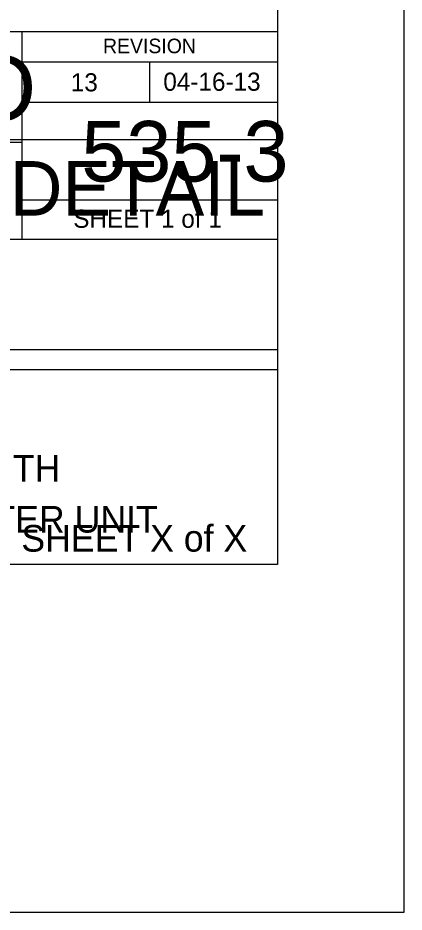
# Model space of a CAD drawing. Extents: x 10133 to 81668, y 2357 to 12713.
# Drawn here: x 13172 to 13490, y 3964 to 4703 of the extents above; entities that cross this region are included whole.
import ezdxf

# ---------------------------------------------------------------- set-up
doc = ezdxf.new("R2010")
doc.units = 0
for name, color, linetype in [('dsnNonPlotable', 7, 'Continuous'), ('dsnStdBlock', 7, 'Continuous'), ('dsnStdBorder', 7, 'Continuous'), ('dsnstdModifiedBlock', 7, 'Continuous'), ('Text', 7, 'Continuous')]:
    doc.layers.add(name, color=color, linetype=linetype)

msp = doc.modelspace()

# ---------------------------------------------------------------- linework, layer by layer
at = {"layer": 'dsnNonPlotable'}
msp.add_lwpolyline([(12697.77, 4691.26), (13385.79, 4691.26), (13385.79, 4251.25), (12697.77, 4251.25)], close=True, dxfattribs=at)
at = {"layer": 'dsnStdBlock'}
for p, q in [((13174.89, 4691.25), (13174.89, 4599.91)), ((13174.89, 4666.31), (13385.81, 4666.31)), ((13280.35, 4666.31), (13280.35, 4633.11)), ((13174.89, 4633.11), (13385.81, 4633.11)), ((12697.79, 4599.91), (13174.89, 4599.91)), ((13174.89, 4599.91), (13174.89, 4519.91)), ((13385.81, 4552.11), (13174.89, 4552.11)), ((12697.79, 4519.91), (13385.81, 4519.91)), ((12697.79, 4428.9), (13385.81, 4428.9))]:
    msp.add_line(p, q, dxfattribs=at)
msp.add_lwpolyline([(12697.79, 4691.25), (13385.81, 4691.25), (13385.81, 4251.24), (12697.79, 4251.24)], close=True, dxfattribs=at)
at = {"layer": 'dsnStdBorder'}
msp.add_lwpolyline([(10250.81, 6261.24), (13385.81, 6261.24), (13385.81, 4251.24), (10250.81, 4251.24)], close=True, dxfattribs=at)
at = {"layer": 'dsnstdModifiedBlock'}
for p, q in [((12697.79, 4602.16), (13385.81, 4602.16)), ((12697.79, 4412.15), (13385.81, 4412.15))]:
    msp.add_line(p, q, dxfattribs=at)
msp.add_lwpolyline([(12697.79, 4691.25), (13385.81, 4691.25), (13385.81, 4251.24), (12697.79, 4251.24)], close=True, dxfattribs=at)
at = {"layer": 'Text'}
msp.add_lwpolyline([(10146.31, 3964.24), (13490.31, 3964.24), (13490.31, 6548.24), (10146.31, 6548.24)], close=True, dxfattribs=at)

# ---------------------------------------------------------------- texts
at = {"layer": 'dsnStdBlock'}
for s, height, p in [('REVISION', 12, (13241.87, 4673.4)), ('13', 15, (13215.28, 4641.88)), ('04-16-13', 15, (13291.63, 4642.36)), ('535-3', 50, (13223.94, 4567.43)), ('ROAD DESIGN DETAIL', 45.0011, (12726.92, 4539.33)), ('SHEET 1 of 1', 15, (13217.3, 4529.26)), ('HOT MIX ASPHALT WITH', 22, (12858.56, 4319.57)), ('6" SLOPED CURB AND GUTTER UNIT', 22, (12764.99, 4277.57))]:
    msp.add_text(s, height=height, dxfattribs=at).set_placement(p)
at = {"layer": 'dsnstdModifiedBlock'}
for s, height, p in [('MODIFIED', 55, (12827.2, 4617.25)), ('SHEET X of X', 22, (13174.49, 4261.87))]:
    msp.add_text(s, height=height, dxfattribs=at).set_placement(p)

doc.saveas('drawing.dxf')
